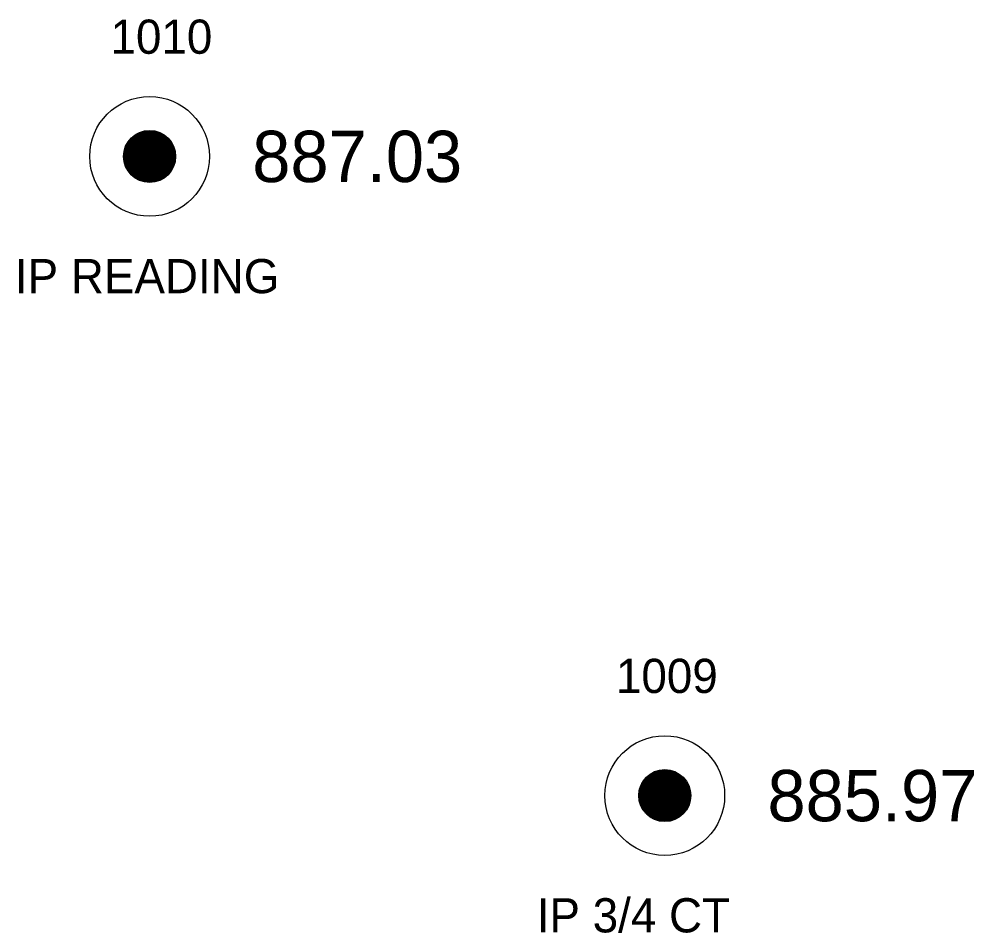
# Model space of a CAD drawing. Extents: x 1622501 to 1626664, y 1117816 to 1121579.
# Drawn here: x 1626051.38 to 1626079.28, y 1121200.16 to 1121226.87 of the extents above; entities that cross this region are included whole.
import ezdxf

# ---------------------------------------------------------------- set-up
doc = ezdxf.new("R2010")
doc.units = 0
for name, color, linetype in [('RD_EX_DV_Prop_txCode', 7, 'Continuous'), ('RD_EX_DV_PropPin', 7, 'Continuous'), ('RD_EX_TX_DV_Prop_ELEV', 7, 'Continuous'), ('RD_SMD_Locator', 7, 'Continuous')]:
    doc.layers.add(name, color=color, linetype=linetype)

msp = doc.modelspace()

# ---------------------------------------------------------------- linework, layer by layer
at = {"layer": 'RD_EX_DV_PropPin'}
for p, q in [((1626054.914, 1121222.152), (1626054.914, 1121223.567)), ((1626054.949, 1121222.139), (1626054.949, 1121223.58)), ((1626054.984, 1121222.128), (1626054.984, 1121223.591)), ((1626055.019, 1121222.119), (1626055.019, 1121223.6)), ((1626055.054, 1121222.111), (1626055.054, 1121223.608)), ((1626055.089, 1121222.106), (1626055.089, 1121223.613)), ((1626055.124, 1121222.102), (1626055.124, 1121223.617)), ((1626055.159, 1121222.099), (1626055.159, 1121223.62)), ((1626055.194, 1121222.098), (1626055.194, 1121223.621)), ((1626055.229, 1121222.099), (1626055.229, 1121223.62)), ((1626055.264, 1121222.102), (1626055.264, 1121223.617)), ((1626055.299, 1121222.106), (1626055.299, 1121223.613)), ((1626055.334, 1121222.111), (1626055.334, 1121223.608)), ((1626055.369, 1121222.119), (1626055.369, 1121223.6)), ((1626055.404, 1121222.128), (1626055.404, 1121223.591)), ((1626055.439, 1121222.139), (1626055.439, 1121223.58)), ((1626055.474, 1121222.152), (1626055.474, 1121223.567)), ((1626054.564, 1121222.433), (1626054.564, 1121223.286)), ((1626054.599, 1121222.385), (1626054.599, 1121223.334)), ((1626054.634, 1121222.344), (1626054.634, 1121223.375)), ((1626054.669, 1121222.309), (1626054.669, 1121223.41)), ((1626054.704, 1121222.277), (1626054.704, 1121223.442)), ((1626054.739, 1121222.25), (1626054.739, 1121223.469)), ((1626054.774, 1121222.225), (1626054.774, 1121223.494)), ((1626054.809, 1121222.203), (1626054.809, 1121223.516)), ((1626054.844, 1121222.184), (1626054.844, 1121223.535)), ((1626054.879, 1121222.167), (1626054.879, 1121223.552)), ((1626055.509, 1121222.167), (1626055.509, 1121223.552)), ((1626055.544, 1121222.184), (1626055.544, 1121223.535)), ((1626055.579, 1121222.203), (1626055.579, 1121223.516)), ((1626055.614, 1121222.225), (1626055.614, 1121223.494)), ((1626055.649, 1121222.25), (1626055.649, 1121223.469)), ((1626055.684, 1121222.277), (1626055.684, 1121223.442)), ((1626055.719, 1121222.309), (1626055.719, 1121223.41)), ((1626055.754, 1121222.344), (1626055.754, 1121223.375)), ((1626055.789, 1121222.385), (1626055.789, 1121223.334)), ((1626055.824, 1121222.433), (1626055.824, 1121223.286)), ((1626054.459, 1121222.663), (1626054.459, 1121223.056)), ((1626054.494, 1121222.562), (1626054.494, 1121223.157)), ((1626054.529, 1121222.49), (1626054.529, 1121223.229)), ((1626055.859, 1121222.49), (1626055.859, 1121223.229)), ((1626055.894, 1121222.562), (1626055.894, 1121223.157)), ((1626055.929, 1121222.663), (1626055.929, 1121223.056)), ((1626069.932, 1121203.48), (1626069.932, 1121204.865)), ((1626069.967, 1121203.465), (1626069.967, 1121204.88)), ((1626070.002, 1121203.452), (1626070.002, 1121204.893)), ((1626070.037, 1121203.441), (1626070.037, 1121204.904)), ((1626070.073, 1121203.432), (1626070.073, 1121204.913)), ((1626070.108, 1121203.425), (1626070.108, 1121204.921)), ((1626070.143, 1121203.419), (1626070.143, 1121204.926)), ((1626070.178, 1121203.415), (1626070.178, 1121204.93)), ((1626070.213, 1121203.412), (1626070.213, 1121204.933)), ((1626070.248, 1121203.412), (1626070.248, 1121204.934)), ((1626070.283, 1121203.412), (1626070.283, 1121204.933)), ((1626070.318, 1121203.415), (1626070.318, 1121204.93)), ((1626070.353, 1121203.419), (1626070.353, 1121204.926)), ((1626070.388, 1121203.425), (1626070.388, 1121204.921)), ((1626070.423, 1121203.432), (1626070.423, 1121204.913)), ((1626070.458, 1121203.441), (1626070.458, 1121204.904)), ((1626070.493, 1121203.452), (1626070.493, 1121204.893)), ((1626070.528, 1121203.465), (1626070.528, 1121204.88)), ((1626070.563, 1121203.48), (1626070.563, 1121204.865)), ((1626069.617, 1121203.746), (1626069.617, 1121204.599)), ((1626069.652, 1121203.698), (1626069.652, 1121204.647)), ((1626069.687, 1121203.658), (1626069.687, 1121204.688)), ((1626069.722, 1121203.622), (1626069.722, 1121204.723)), ((1626069.757, 1121203.59), (1626069.757, 1121204.755)), ((1626069.792, 1121203.563), (1626069.792, 1121204.782)), ((1626069.827, 1121203.538), (1626069.827, 1121204.807)), ((1626069.862, 1121203.516), (1626069.862, 1121204.829)), ((1626069.897, 1121203.497), (1626069.897, 1121204.848)), ((1626070.598, 1121203.497), (1626070.598, 1121204.848)), ((1626070.633, 1121203.516), (1626070.633, 1121204.829)), ((1626070.668, 1121203.538), (1626070.668, 1121204.807)), ((1626070.703, 1121203.563), (1626070.703, 1121204.782)), ((1626070.738, 1121203.59), (1626070.738, 1121204.755)), ((1626070.773, 1121203.622), (1626070.773, 1121204.723)), ((1626070.808, 1121203.658), (1626070.808, 1121204.688)), ((1626070.843, 1121203.698), (1626070.843, 1121204.647)), ((1626070.878, 1121203.746), (1626070.878, 1121204.599)), ((1626069.512, 1121203.976), (1626069.512, 1121204.369)), ((1626069.547, 1121203.875), (1626069.547, 1121204.471)), ((1626069.582, 1121203.803), (1626069.582, 1121204.542)), ((1626070.913, 1121203.803), (1626070.913, 1121204.542)), ((1626070.948, 1121203.875), (1626070.948, 1121204.471)), ((1626070.983, 1121203.976), (1626070.983, 1121204.369))]:
    msp.add_line(p, q, dxfattribs=at)
for centre, radius in [((1626055.194, 1121222.859), 1.75), ((1626055.194, 1121222.859), 0.761), ((1626070.248, 1121204.173), 1.75), ((1626070.248, 1121204.173), 0.761)]:
    msp.add_circle(centre, radius, dxfattribs=at)
at = {"layer": 'RD_SMD_Locator'}
for centre in [(1626055.194, 1121222.859), (1626070.248, 1121204.173)]:
    msp.add_circle(centre, 0.15, dxfattribs=at)

# ---------------------------------------------------------------- texts
at = {"layer": 'RD_EX_DV_Prop_txCode'}
for s, p in [('1010', (1626054.052, 1121225.86)), ('IP READING', (1626051.257, 1121218.86)), ('1009', (1626068.822, 1121207.173)), ('IP 3/4 CT', (1626066.507, 1121200.173))]:
    msp.add_text(s, height=1, dxfattribs=at).set_placement(p)
at = {"layer": 'RD_EX_TX_DV_Prop_ELEV'}
for s, p in [('887.03', (1626058.194, 1121222.11)), ('885.97', (1626073.248, 1121203.423))]:
    msp.add_text(s, height=1.5, dxfattribs=at).set_placement(p)

doc.saveas('drawing.dxf')
